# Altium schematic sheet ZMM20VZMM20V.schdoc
size 127 x 101 mm
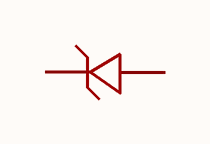
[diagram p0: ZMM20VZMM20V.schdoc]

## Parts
U?  zmm20v  [LL-34_L3.5-W1.5-R-RD]  (value not drawn)

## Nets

Not connected (* = marked no-connect by the designer): U? 1(A) 2(K)

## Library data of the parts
U? = zmm20v: 二极管配置:1个独立式;稳压值(标称值):20V;稳压值(范围值):18.8V~21.2V;耗散功率(Pd):500mW;; Manufacturer: JSMSEMI(杰盛微); AddInBom: yes; ModelId: cd327e8d456a4c47960b8e28abf831c1; ModelName: LL-34_L3.7-W1.6; ModelTransform: 145.74774,62.96633,0,0,0,0,-0.0005,0,0; Diode Configuration: 1个独立式; Zener Voltage(Nom): 20V; Reverse Leakage Current (Ir): 100nA@15V; Pd - Power Dissipation: 500mW; Impedance(Zzt): 55Ω; Impedance(Zzk): 220Ω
